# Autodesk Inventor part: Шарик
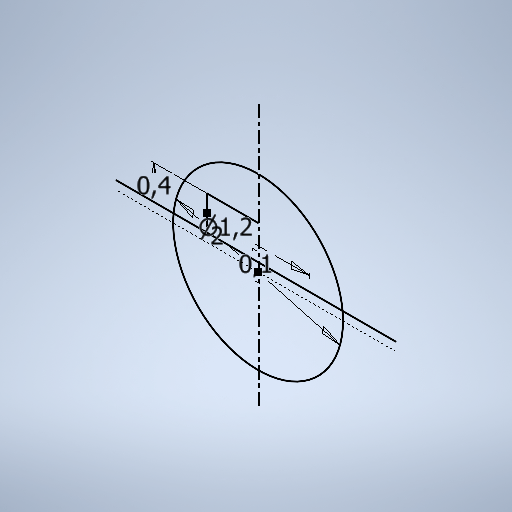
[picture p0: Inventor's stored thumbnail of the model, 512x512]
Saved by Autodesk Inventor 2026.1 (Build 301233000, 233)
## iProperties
Created: 2026-01
Part Number: Шарик
Material: Типовые
Document SubType Name: Modeling
Designer: Yury Melnikov
Density: 1 g/cm^3
Appearance: По умолчанию
Author: Yury Melnikov
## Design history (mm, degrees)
sketch "Эскиз1"
  geometry: L1 (-1.671, 0)-(1.622, 0); L2 (-1.671, 0.1)-(1.622, 0.1); L3 (0, 1.711)-(0, -1.41); L4 (-0.6, 0.1)-(-0.6, 0.5); L5 (-0.6, 0.5)-(0, 0.5); C1 r 1 at (0, 0); 2 further points
  constraints: 10 end point, 4 point on line, 2 vertical, 1 centre point, 1 coincident, 1 horizontal, 1 midpoint, 1 parallel, 1 perpendicular
  dimensions: "d0" = 2 diameter of C1; "d1" = 0.1 distance between parallel lines of L1 L2; "d2" = 0.4 distance of L4.start L4.end; "d3" = 1.2 diameter of point (-0.6, 0.3) L3
